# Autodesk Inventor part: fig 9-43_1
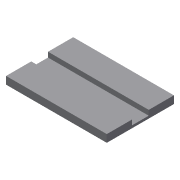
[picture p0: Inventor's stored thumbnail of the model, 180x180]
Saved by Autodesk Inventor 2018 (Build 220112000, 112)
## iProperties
Created: 2013-03
Part Number: fig 9-43_1
Material: Generic
Document SubType Name: Modeling
Designer: CADCIM
Density: 1 g/cm^3
Appearance: Default
Author: CADCIM
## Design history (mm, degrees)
sketch "Sketch1"
  geometry: L1 (-12.966, 10)-(17.034, 10); L2 (17.034, 10)-(17.034, -10); L3 (17.034, -10)-(-12.966, -10); L4 (-12.966, -10)-(-12.966, 10); 1 further point
  constraints: 8 end point, 2 parallel, 1 horizontal, 1 perpendicular
  dimensions: "d0" = 30 distance of L1.start L1.end; "d2" = 20 distance of L1.end L2.end
extrude "Extrusion1" new body sketch "Sketch1" distance "d3" = 2.25; taper "d4" = 0 deg
sketch "Sketch2"
  geometry: L1 (-12.966, 10)-(-12.966, -10) reference; L2 (-12.966, 2.498)-(87.034, 2.498); L3 (87.034, 2.498)-(87.034, -2.502); L4 (87.034, -2.502)-(-12.966, -2.502); L5 (-12.966, -2.502)-(-12.966, 2.498); 1 further point
  constraints: 8 end point, 2 parallel, 1 horizontal, 1 perpendicular, 1 point on line
  dimensions: "d5" = 5 distance of L2.end L3.end; "d7" = 100 distance of L2.start L2.end
extrude "Extrusion2" cut sketch "Sketch2" distance "d8" = 1.5; taper "d9" = 0 deg
body "Solid1"
